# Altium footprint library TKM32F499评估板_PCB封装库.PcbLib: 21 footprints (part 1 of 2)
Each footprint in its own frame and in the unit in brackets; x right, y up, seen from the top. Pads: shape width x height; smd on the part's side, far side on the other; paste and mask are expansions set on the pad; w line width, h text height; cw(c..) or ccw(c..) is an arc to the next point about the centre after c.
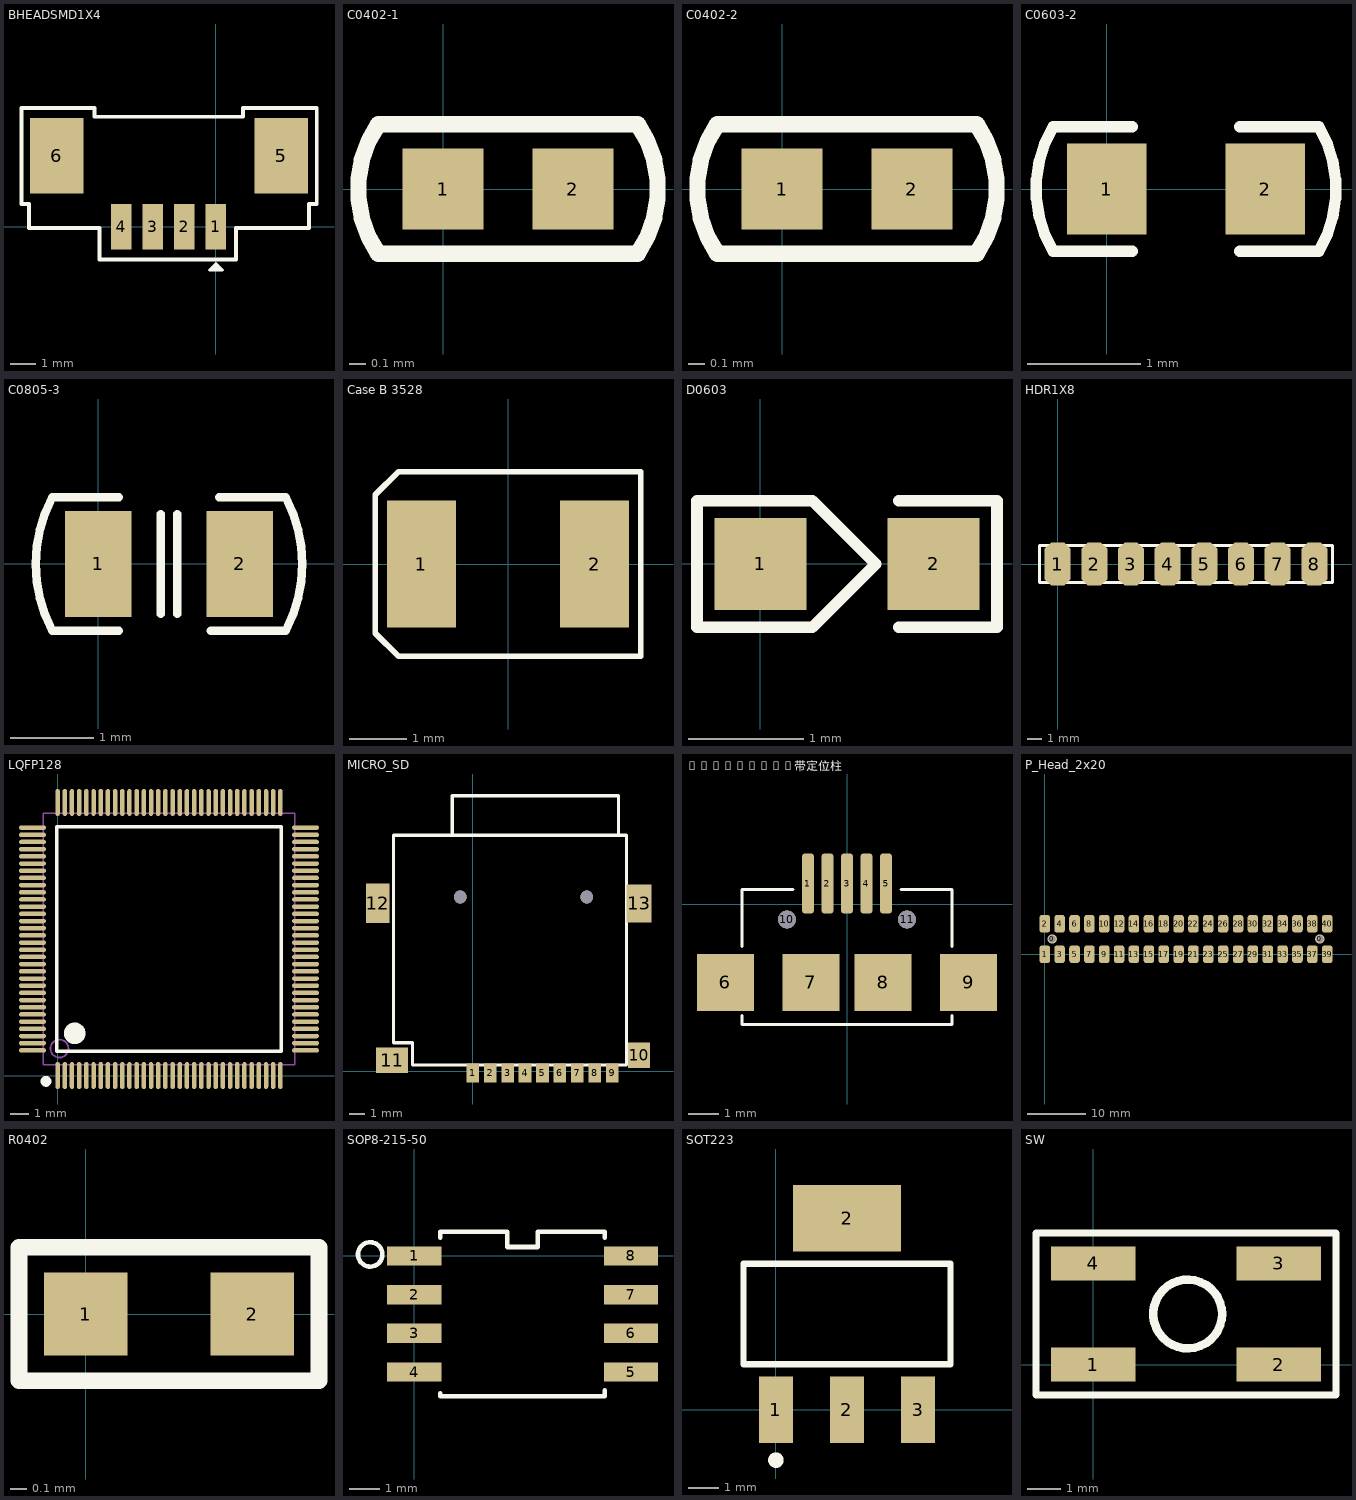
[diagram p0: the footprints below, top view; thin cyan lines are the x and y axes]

## BHEADSMD1X4 [mil]
pads (6):
  rect 32x71 smd: 1(0,0) 2(-49.21,0) 3(-98.43,0) 4(-147.64,0)
  rect 83x118 smd: 5(102.36,110.24) 6(-248.03,110.24)
Top Overlay:
  lines w5: 4.5,-63.9 -1.5,-63.9 ; -1.5,-63.9 -1.5,-61.9 0.5,-61.9 ; -1.5,-63.9 -1.5,-65.9 0.5,-65.9 2.5,-63.9 0.5,-61.9 ; -1.5,-63.9 0.5,-61.9 ; 0.5,-61.9 4.5,-65.9 -5.5,-65.9 0.5,-59.9 8.5,-67.9 10.5,-67.9 ; 10.5,-67.9 0.5,-57.9 -9.5,-67.9 10.5,-67.9
  lines w6: -303.15,35.2 -303.15,185.2 -188.98,185.2 -188.98,171.4 42.9,171.4 42.9,185.2 157.9,185.2 157.9,35.2 145.67,35.2 145.67,-2.2 32,-2.2 32,-51.5 -181.1,-51.5 -181.1,-2.2 -291.34,-2.2 -291.34,35.2 -303.15,35.2
3D body: height 133.86, standoff -0.2, extent -266.73,-31.89 117.13,181.1

## C0402-1 [mm]
pads (2):
  rect 0.5x0.5 smd mask+0.1: 1(0,0) 2(0.8,0)
Top Overlay:
  lines w0.1: 1.2,-0.4 -0.4,-0.4 cw(c0.178,0) -0.4,0.4 1.2,0.4 cw(c0.627,0.001) 1.2,-0.398
3D body: height 0.51, standoff 0, extent -0.108,-0.254 0.908,0.254

## C0402-2 [mm]
pads (2):
  rect 0.5x0.5 smd mask+0.1: 1(0,0) 2(0.8,0)
Top Overlay:
  lines w0.1: 1.2,-0.4 -0.4,-0.4 cw(c0.178,0) -0.4,0.4 1.2,0.4 cw(c0.627,0.001) 1.2,-0.398
3D body: height 0.2, standoff 0, extent -0.1,-0.3 0.9,0.3

## C0603-2 [mm]
pads (2):
  rect 0.7x0.8 smd mask+0.1: 1(0,0) 2(1.4,0)
Top Overlay:
  lines w0.1: 0.225,-0.55 -0.475,-0.55 cw(c0.458,0) -0.475,0.55 0.225,0.55 ; 1.175,-0.55 1.875,-0.55 ccw(c0.942,0) 1.875,0.55 1.175,0.55
3D body: height 0.3, standoff 0, extent -0.1,-0.4 1.5,0.4

## C0805-3 [mm]
pads (2):
  rect 0.8x1.27 smd mask+0.1: 1(0,0) 2(1.7,0)
Top Overlay:
  lines w0.1: 0.25,-0.8 -0.55,-0.8 cw(c0.95,0) -0.55,0.8 0.25,0.8 ; 0.75,-0.6 0.75,0.6 ; 0.95,-0.6 0.95,0.6 ; 1.35,-0.8 2.25,-0.8 ccw(c0.75,0) 2.25,0.8 1.45,0.8
3D body: height 1.2, standoff 0, extent -0.15,-0.6 1.85,0.6

## Case B 3528 [mm]
pads (2):
  rect 1.2x2.2 smd: 1(-1.5,0) 2(1.5,0)
Top Overlay:
  lines w0.1: -2.3,-1.2 -1.9,-1.6 2.3,-1.6 2.3,1.6 -1.9,1.6 -2.3,1.2 -2.3,-1.2
3D body: height 2.09, standoff -0.01, extent -1.845,-1.4 1.845,1.42

## D0603 [mm]
pads (2):
  rect 0.8x0.8 smd mask+0.1: 1(0,0) 2(1.5,0)
Top Overlay:
  lines w0.1: 1.2,-0.55 2.05,-0.55 2.05,0.55 1.2,0.55 ; -0.55,-0.55 0.3,-0.55 0.45,-0.55 1,0 0.45,0.55 0.3,0.55 -0.55,0.55 -0.55,-0.55
3D body: height 0.85, standoff 0.01, extent -0.259,-0.46 1.803,0.447

## HDR1X8 [mm]
pads (8):
  oct 1.8x3 smd: 1(0,0) 2(2.54,0) 3(5.08,0) 4(7.62,0) 5(10.16,0) 6(12.7,0) 7(15.24,0) 8(17.78,0)
Top Overlay:
  lines w0.2: -1.27,-1.27 -1.27,1.27 19.05,1.27 19.05,-1.27 -1.27,-1.27

## LQFP128 [mm]
pads (128):
  oval 0.25x1.5 smd mask+0.051: 1(0,0) 2(0.4,0) 3(0.8,0) 4(1.2,0) 5(1.6,0) 6(2,0) 7(2.4,0) 8(2.8,0) 9(3.2,0) 10(3.6,0) 11(4,0) 12(4.4,0) 13(4.8,0) 14(5.2,0) 15(5.6,0) 16(6,0) 17(6.4,0) 18(6.8,0) 19(7.2,0) 20(7.6,0) 21(8,0) 22(8.4,0) 23(8.8,0) 24(9.2,0) 25(9.6,0) 26(10,0) 27(10.4,0) 28(10.8,0) 29(11.2,0) 30(11.6,0) 31(12,0) 32(12.4,0) 65(12.4,15.2) 66(12,15.2) 67(11.6,15.2) 68(11.2,15.2) 69(10.8,15.2) 70(10.4,15.2) 71(10,15.2) 72(9.6,15.2) 73(9.2,15.2) 74(8.8,15.2) 75(8.4,15.2) 76(8,15.2) 77(7.6,15.2) 78(7.2,15.2) 79(6.8,15.2) 80(6.4,15.2) 81(6,15.2) 82(5.6,15.2) 83(5.2,15.2) 84(4.8,15.2) 85(4.4,15.2) 86(4,15.2) 87(3.6,15.2) 88(3.2,15.2) 89(2.8,15.2) 90(2.4,15.2) 91(2,15.2) 92(1.6,15.2) 93(1.2,15.2) 94(0.8,15.2) 95(0.4,15.2) 96(0,15.2)
  oval 1.5x0.25 smd mask+0.051: 33(13.8,1.4) 34(13.8,1.8) 35(13.8,2.2) 36(13.8,2.6) 37(13.8,3) 38(13.8,3.4) 39(13.8,3.8) 40(13.8,4.2) 41(13.8,4.6) 42(13.8,5) 43(13.8,5.4) 44(13.8,5.8) 45(13.8,6.2) 46(13.8,6.6) 47(13.8,7) 48(13.8,7.4) 49(13.8,7.8) 50(13.8,8.2) 51(13.8,8.6) 52(13.8,9) 53(13.8,9.4) 54(13.8,9.8) 55(13.8,10.2) 56(13.8,10.6) 57(13.8,11) 58(13.8,11.4) 59(13.8,11.8) 60(13.8,12.2) 61(13.8,12.6) 62(13.8,13) 63(13.8,13.4) 64(13.8,13.8) 97(-1.4,13.8) 98(-1.4,13.4) 99(-1.4,13) 100(-1.4,12.6) 101(-1.4,12.2) 102(-1.4,11.8) 103(-1.4,11.4) 104(-1.4,11) 105(-1.4,10.6) 106(-1.4,10.2) 107(-1.4,9.8) 108(-1.4,9.4) 109(-1.4,9) 110(-1.4,8.6) 111(-1.4,8.2) 112(-1.4,7.8) 113(-1.4,7.4) 114(-1.4,7) 115(-1.4,6.6) 116(-1.4,6.2) 117(-1.4,5.8) 118(-1.4,5.4) 119(-1.4,5) 120(-1.4,4.6) 121(-1.4,4.2) 122(-1.4,3.8) 123(-1.4,3.4) 124(-1.4,3) 125(-1.4,2.6) 126(-1.4,2.2) 127(-1.4,1.8) 128(-1.4,1.4)
Top Overlay:
  circle w0.6: c0.95,2.35 r0.3
  circle w0.3: c-0.65,-0.325 r0.15
  lines w0.2: -0.05,1.35 12.45,1.35 12.45,13.85 -0.05,13.85 -0.05,1.35
Mechanical 13:
  circle w0.1: c0.1,1.5 r0.5
  lines w0.1: -0.8,0.6 -0.8,14.6 13.2,14.6 13.2,0.6 -0.8,0.6
3D body: height 1.45, standoff 0.1, extent -1.8,-0.4 14.2,15.6

## MICRO_SD [mm]
pads (13):
  rect 0.8x1.2 smd: 1(0,-0.1) 2(1.1,-0.1) 3(2.2,-0.1) 4(3.3,-0.1) 5(4.4,-0.1) 6(5.5,-0.1) 7(6.6,-0.1) 8(7.7,-0.1) 9(8.8,-0.1)
  rect 1.4x1.6 smd: 10(10.5,1)
  rect 2x1.6 smd: 11(-5.1,0.7)
  rect 1.5x2.5 smd: 12(-6,10.6)
  rect 1.6x2.4 smd: 13(10.5,10.6)
via 7.2,11 diameter 0.8 hole 0.8
via -0.8,11 diameter 0.8 hole 0.8
Top Overlay:
  lines w0.2: -1.3,14.9 -1.3,17.4 9.2,17.4 9.2,14.9 ; -5,1.8 -3.8,1.8 -3.8,0.4 9.7,0.4 9.7,14.9 -5,14.9 -5,1.8
3D body: height 1.85, standoff -0.6, extent -5.75,-0.4 10.25,14.85

## MICROUSB_带定位柱 [mm]
pads (11):
  rrect50% 0.4x2 smd: 1(-1.3,0.7) 2(-0.65,0.7) 3(0,0.7)
  rrect50% 0.4x2 smd mask+0.1: 4(0.65,0.7) 5(1.3,0.7)
  rect 1.9x1.9 smd: 6(-4.05,-2.6) 7(-1.2,-2.6) 8(1.2,-2.6) 9(4.05,-2.6)
  round 0.6 hole 0.6: 10(-2,-0.5) 11(2,-0.5)
Top Overlay:
  lines w0.1: -3.5,-3.7 -3.5,-4 3.5,-4 3.5,-3.7 ; -3.5,-1.4 -3.5,-0.6 -3.5,0.5 -1.8,0.5 ; 1.8,0.5 3.5,0.5 3.5,-0.6 3.5,-1.4
3D body: height 2.79, standoff -0.28, extent -4.4,-5.116 4.4,0.509

## P_Head_2x20 [mm]
pads (42):
  round 1.6 hole 1.2: 0(1.27,2.6) 0(46.99,2.6)
  rrect50% 1.8x3 smd: 1(0,0) 2(0,5.2) 3(2.54,0) 4(2.54,5.2) 5(5.08,0) 6(5.08,5.2) 7(7.62,0) 8(7.62,5.2) 9(10.16,0) 10(10.16,5.2) 11(12.7,0) 12(12.7,5.2) 13(15.24,0) 14(15.24,5.2) 15(17.78,0) 16(17.78,5.2) 17(20.32,0) 18(20.32,5.2) 19(22.86,0) 20(22.86,5.2) 21(25.4,0) 22(25.4,5.2) 23(27.94,0) 24(27.94,5.2) 25(30.48,0) 26(30.48,5.2) 27(33.02,0) 28(33.02,5.2) 29(35.56,0) 30(35.56,5.2) 31(38.1,0) 32(38.1,5.2) 33(40.64,0) 34(40.64,5.2) 35(43.18,0) 36(43.18,5.2) 37(45.72,0) 38(45.72,5.2) 39(48.26,0) 40(48.26,5.2)

## R0402 [mm]
pads (2):
  rect 0.5x0.5 smd mask+0.1: 1(0,0) 2(1,0)
Top Overlay:
  lines w0.1: -0.4,-0.4 -0.4,0.4 1.4,0.4 1.4,-0.4 -0.4,-0.4
3D body: height 0.35, standoff 0, extent 0,-0.25 1,0.25

## SOP8-215-50 [mil]
pads (8):
  rect 70x25 smd: 1(0,0) 2(0,-50) 3(0,-100) 4(0,-150) 5(280,-150) 6(280,-100) 7(280,-50) 8(280,0)
Top Overlay:
  circle w6: c-57,2 r15.75
  lines w6: 33.7,-177.36 33.7,-181.3 246.3,-181.3 246.3,-173.43 ; 33.7,23.43 33.7,31.3 120.31,31.3 120.31,11.61 159.69,11.61 159.69,31.3 246.3,31.3 246.3,23.43
3D body: height -15.75, standoff -82.68, extent 23.63,-171.26 259.85,21.65

## SOT223 [mm]
pads (4):
  rect 1.1x2.15 smd: 1(0,0) 2(2.3,0) 3(4.6,0)
  rect 3.5x2.15 smd: 2(2.3,6.2)
Top Overlay:
  circle w0.25: c0,-1.625 r0.125
  lines w0.2: -1.05,1.475 -1.05,4.725 5.65,4.725 5.65,1.475 -1.05,1.475
3D body: height 1.7, standoff 0, extent -0.8,-0.4 5.4,6.6

## SW [mm]
pads (4):
  rect 2.5x1 smd: 1(0,0) 2(5.5,0) 3(5.5,3) 4(0,3)
Top Overlay:
  circle w0.254: c2.8,1.5 r1.02
  lines w0.2: -1.7,-0.9 7.2,-0.9 7.2,3.9 -1.7,3.9 -1.7,-0.9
